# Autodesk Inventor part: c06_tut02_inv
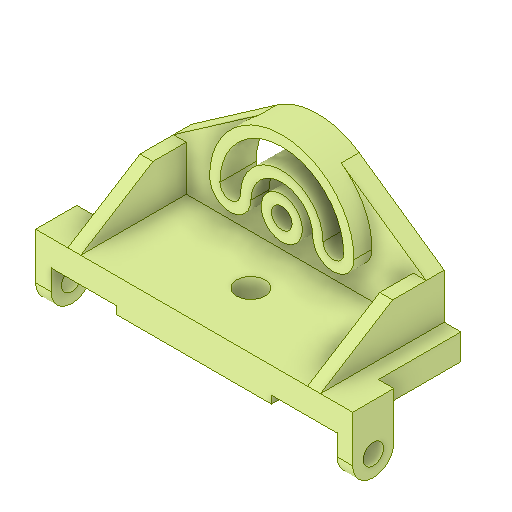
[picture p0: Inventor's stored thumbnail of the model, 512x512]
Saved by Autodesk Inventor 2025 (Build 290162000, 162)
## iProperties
Created: 2015-03
Part Number: c06_tut02_inv
Material: Generic
Document SubType Name: Modeling
Designer: Sandeep
Density: 1 g/cm^3
Appearance: Zinc Chromate 2
Author: Sandeep
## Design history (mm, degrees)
sketch "Sketch1"
  geometry: L1 (0, 0)-(-51, 0); L2 (-51, 0)-(-51, -6); L3 (-51, -6)-(-171, -6); L4 (-171, -6)-(-171, 0); L5 (-171, 0)-(-222, 0); L6 (-222, 0)-(-222, 20); L7 (-222, 20)-(0, 20); L8 (0, 20)-(0, 0)
  constraints: 16 end point, 6 perpendicular, 2 point on line, 1 horizontal
  dimensions: "d0" = 20 distance of L5.end L6.end; "d1" = 26 distance between parallel lines of L3 L7; "d2" = 120 distance of L4.end L1.end; "d3" = 51 distance between parallel lines of L2 L8; "d4" = 51 distance from line of L4.end L6
extrude "Extrusion1" new body sketch "Sketch1" distance "d5" = 96; taper "d6" = 0 deg
sketch "Sketch2"
  geometry: L1 (209, -20)-(209, -55); L2 (209, -55)-(143, -100.957); L3 (79, -100.957)-(13, -55); L4 (13, -55)-(13, -20); L5 (222, -20)-(0, -20) reference; L6 (13, -20)-(209, -20); L7 (222, -20)-(222, 0) reference; L8 (209, -55)-(-58.567, -55); A1 r 56 centre (111, -55) between (79, -100.957) and (143, -100.957); 1 further point
  constraints: 12 end point, 2 parallel, 2 point on circle, 2 point on line, 2 tangent, 1 centre point, 1 collinear, 1 horizontal, 1 vertical
  dimensions: "d7" = 13 distance from line of point (0, 0) L4; "d8" = 13 distance between parallel lines of L1 L7; "d10" = 56 radius of A1; "d11" = 98 distance from line of L1 A1.centre; "d13" = 35 distance of L1.start L1.end
extrude "Extrusion2" join sketch "Sketch2" distance "d14" = 14; taper "d15" = 0 deg
sketch "Sketch4"
  geometry: L1 (111, 55)-(-9.927, 55); C1 r 16 at (111, 55); A1 r 40 centre (111, 55) between (151, 55) and (71, 55); A2 r 56 centre (111, 55) between (167, 55) and (55, 55); A3 r 24 centre (111, 55) between (135, 55) and (87, 55); A4 r 16 centre (151, 55) between (135, 55) and (167, 55); A5 r 16 centre (71, 55) between (55, 55) and (87, 55); A6 r 56 centre (111, 55) between (143, 100.957) and (79, 100.957) reference
  constraints: 10 point on circle, 6 centre point, 4 tangent, 2 end point, 2 point on line, 1 coincident, 1 concentric, 1 horizontal
  dimensions: "d20" = 56 radius of A2; "d21" = 24 radius of A3; "d22" = 32 diameter of C1
extrude "Extrusion3" join sketch "Sketch4" distance "d23" = 14; taper "d24" = 0 deg
sketch "Sketch7"
  geometry: C1 r 8 at (111, 55); A1 r 16 centre (151, 55) between (135, 55) and (167, 55) reference; A2 r 16 centre (71, 55) between (55, 55) and (87, 55) reference; A3 r 40 centre (111, 55) between (151, 55) and (71, 55); A4 r 48 centre (111, 55) between (159, 55) and (63, 55); A5 r 32 centre (111, 55) between (143, 55) and (79, 55); A6 r 8 centre (151, 55) between (143, 55) and (159, 55); A7 r 8 centre (71, 55) between (63, 55) and (79, 55); A8 r 56 centre (111, 55) between (167, 55) and (55, 55) reference; 1 further point
  constraints: 10 point on circle, 6 centre point, 4 tangent, 1 coincident, 1 concentric
  dimensions: "d26" = 8 radius of A6; "d27" = 16 diameter of C1
extrude "Extrusion4" cut sketch "Sketch7" extent not by distance; stored distance "d28" = 14; taper "d29" = 0 deg
workplane "Work Plane1"
sketch "Sketch12"
  geometry: L1 (35, -96)-(35, 0) reference; L2 (35, -13.954)-(35, -96); L3 (35, -96)-(0, -40); L4 (0, -40)-(0, -14); L5 (0, 0)-(-45.957, 0) reference; 1 further point
  constraints: 6 end point, 1 collinear, 1 parallel, 1 point on line
  dimensions: "d34" = 35 distance between parallel lines of L1 L4; "d35" = 40 distance from line of L5 L3.end
feature "Rib1" sketch "Sketch12" dims "d36" = 1, "d37" = 10, "d38" = 0, "d39" = 0, "d40" = 1, "d41" = 1
sketch "Sketch14"
  geometry: L1 (0, 0)-(0, 32); L2 (0, 32)-(36, 32); L3 (36, 0)-(0, 0); L4 (0, 96)-(0, 0) reference; C1 r 8 at (36, 16); A1 r 16 centre (36, 16) between (36, 0) and (36, 32); 1 further point
  constraints: 6 end point, 2 centre point, 2 point on circle, 2 tangent, 1 coincident, 1 horizontal, 1 perpendicular, 1 point on line
  dimensions: "d42" = 36 distance from line of L1 A1.centre; "d43" = 16 radius of A1; "d44" = 16 diameter of C1
extrude "Extrusion5" join sketch "Sketch14" distance "d45" = 12; taper "d46" = 0 deg
workplane "Work Plane2"
mirror "Mirror1"
sketch "Sketch15"
  geometry: L1 (-176, 82)-(-176, 0) reference; L2 (0, 82)-(-176, 82) reference; 1 further point
  dimensions: "d48" = 88 distance from line of L1 point (-88, 44); "d49" = 38 distance from line of L2 point (-88, 44)
hole "Hole1" sketch "Sketch15" at (-88, 44) diameter "d50" = 22; stored, may be unused: countersink angle "d54" = 90 deg, drill point angle "d56" = 118 deg; dims "d51" = 6, "d52" = 4, "d53" = 2, "d55" = 8
body "Solid1"
other parameters: "d32" = 0, "d47" = -111
